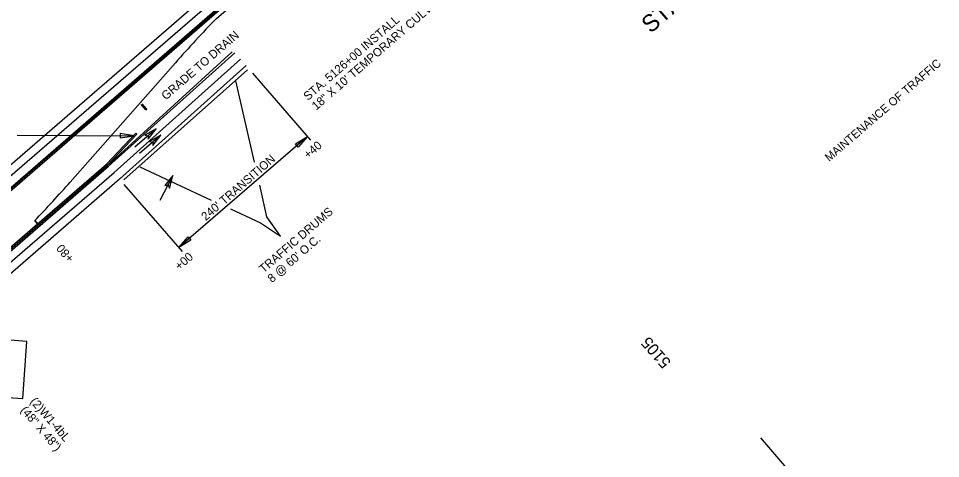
# Model space of a CAD drawing. Extents: x 259983 to 267998, y 211467 to 219827.
# Drawn here: x 262447 to 263749, y 217501 to 218123 of the extents above; entities that cross this region are included whole.
import ezdxf

# ---------------------------------------------------------------- set-up
doc = ezdxf.new("R2010")
doc.units = 0
for name, color, linetype in [('1', 7, 'Continuous'), ('DRAINAGE', 7, 'Continuous'), ('Level 1', 7, 'Continuous'), ('Level 43', 7, 'Continuous'), ('Level 58', 7, 'Continuous'), ('Level 6', 7, 'Continuous'), ('R_MOT', 7, 'Continuous'), ('R_MOT STAGE 1', 7, 'Continuous'), ('R_MOT STAGE 2', 7, 'Continuous'), ('STATIONING1', 7, 'Continuous')]:
    doc.layers.add(name, color=color, linetype=linetype)

msp = doc.modelspace()

# ---------------------------------------------------------------- linework, layer by layer
at = {"layer": '1'}
msp.add_line((262445.1, 217958), (262610.6, 217957), dxfattribs=at)
for points in [[(262780.2, 217919.9), (262753.9, 218034.7)], [(262618.6, 217913.1), (262719.3, 217866.3)], [(262746.3, 217853.8), (262788.8, 217834.1), (262816.9, 217815.5), (262797.9, 217842.7), (262787.7, 217887.4)]]:
    msp.add_lwpolyline(points, dxfattribs=at)
for points in [[(262590.8, 217954.1), (262610.6, 217957), (262590.8, 217960.1)], [(262838.2, 217945.5), (262855.1, 217956.2), (262842.1, 217941)], [(262690.6, 217809.8), (262673.7, 217799.1), (262686.7, 217814.3)]]:
    msp.add_lwpolyline(points, close=True, dxfattribs=at)
at = {"layer": 'DRAINAGE'}
for p, q in [((262627, 217993.6), (262620.4, 218001.2)), ((262628.1, 217994.6), (262621.6, 218002.2)), ((262627, 217993.6), (262628.1, 217994.6))]:
    msp.add_line(p, q, dxfattribs=at)
at = {"layer": 'Level 43'}
for points in [[(262641.6, 217966.8), (262611.5, 217940.8)], [(262648.1, 217958), (262618.1, 217932.1)], [(262665.2, 217900.9), (262646.8, 217865.6)]]:
    msp.add_lwpolyline(points, dxfattribs=at)
at = {"layer": 'Level 58'}
for points in [[(262630.4, 217952.1), (262641.6, 217966.8), (262625.5, 217957.8), (262630.2, 217956.9)], [(262637, 217943.4), (262648.1, 217958), (262632.1, 217949.1), (262636.8, 217948.2)], [(262660.2, 217883.2), (262665.2, 217900.9), (262653.5, 217886.6), (262658.2, 217887.6)]]:
    msp.add_lwpolyline(points, close=True, dxfattribs=at)
at = {"layer": 'R_MOT'}
for p, q in [((262459, 217666.7), (262378.2, 217672.5)), ((262453.2, 217585.9), (262459, 217666.7)), ((262372.4, 217591.7), (262453.2, 217585.9))]:
    msp.add_line(p, q, dxfattribs=at)
at = {"layer": 'R_MOT STAGE 1'}
for p, q in [((262072.1, 217601.2), (262850.7, 218275.2)), ((262844.1, 218235.1), (261603.1, 217160.8)), ((262845.4, 218233.6), (261604.4, 217159.3)), ((262845.4, 218233.6), (262530.8, 217961.2)), ((262726.5, 218122.7), (262849.3, 218229.1)), ((262782.9, 218200.4), (261594, 217171.3)), ((261601.8, 217162.3), (262790.6, 218191.5)), ((262574, 217914), (262752.7, 218074.1)), ((262575.3, 217917), (262748.9, 218075.7)), ((262520, 217891.7), (262668.7, 218060.2)), ((262582, 217905), (262760.8, 218065.1)), ((262590, 217896.1), (262768.8, 218056.2)), ((262595.9, 217894.9), (262770.7, 218050.2)), ((262522.7, 217954.3), (262302.4, 217763.5)), ((262530.8, 217961.2), (262522.7, 217954.3)), ((262612.6, 217960.6), (262571.3, 217917)), ((262614, 217959.2), (262572.8, 217915.6)), ((262612.6, 217960.6), (262614, 217959.2)), ((261685.6, 217150.2), (262571.3, 217917)), ((261686.9, 217148.7), (262572.7, 217915.5)), ((261688.2, 217147.1), (262574.1, 217914.1)), ((262571.3, 217917), (262572.8, 217915.6)), ((262572.7, 217915.5), (262571.3, 217917)), ((262009, 217409), (262582.1, 217905.1)), ((262016.8, 217399.9), (262589.9, 217896.1)), ((262470, 217837.2), (262473.9, 217832.7)), ((262473.9, 217832.7), (262470, 217837.2)), ((261865.1, 217305.6), (262473.9, 217832.7)), ((263662.2, 217337.5), (263495.2, 217530.4))]:
    msp.add_line(p, q, dxfattribs=at)
for centre, radius, start, end in [((264088.6, 216806.9), 1893.9, 135.9906, 138.5667), ((261076.2, 219166.2), 1925.9, 316.3658, 318.5667)]:
    msp.add_arc(centre, radius, start, end, dxfattribs=at)
at = {"layer": 'R_MOT STAGE 2'}
for p, q in [((262860, 217950.6), (262777.9, 218045.4)), ((262855.1, 217956.2), (262673.7, 217799.1)), ((262678.5, 217793.5), (262596.5, 217888.3))]:
    msp.add_line(p, q, dxfattribs=at)

# ---------------------------------------------------------------- texts
at = {"layer": '1'}
for s, rotation, p in [("240' TRANSITION", 40.8733, (262711.5, 217836.4)), ('TRAFFIC DRUMS', 40.8921, (262793.3, 217762.5)), ("8 @ 60' O.C.", 40.8921, (262805.1, 217748.9))]:
    msp.add_text(s, height=12, rotation=rotation, dxfattribs=at).set_placement(p)
at = {"layer": 'DRAINAGE'}
for s, p in [('18" X 10\' TEMPORARY CULV\'T.', (262867.6, 217992.5)), ('STA. 5126+00 INSTALL', (262855.9, 218006.1)), ('GRADE TO DRAIN', (262655.2, 218006.8))]:
    msp.add_text(s, height=12, rotation=40.8833, dxfattribs=at).set_placement(p)
at = {"layer": 'Level 1'}
msp.add_text('MAINTENANCE OF TRAFFIC', height=11.7, rotation=40.8733, dxfattribs=at).set_placement((263592, 217919.9))
at = {"layer": 'Level 6'}
msp.add_text('STAGE 1B - SHELL LAKE', height=24, rotation=40.8733, dxfattribs=at).set_placement((263339.8, 218100.7))
at = {"layer": 'R_MOT'}
for s, p in [('(2)W1-4bL', (262462.7, 217581.4)), ('(48" X 48")', (262449.1, 217569))]:
    msp.add_text(s, height=12, rotation=310.8833, dxfattribs=at).set_placement(p)
at = {"layer": 'R_MOT STAGE 2'}
for s, rotation, p in [('+40', 40.8821, (262856.1, 217923.9)), ('+80', 130.8821, (262526.4, 217784.6)), ('+00', 40.8821, (262674.3, 217766.5))]:
    msp.add_text(s, height=12, rotation=rotation, dxfattribs=at).set_placement(p)
at = {"layer": 'STATIONING1'}
msp.add_text('5105', height=16.5, rotation=130.8833, dxfattribs=at).set_placement((263369.5, 217637.6))

doc.saveas('drawing.dxf')
